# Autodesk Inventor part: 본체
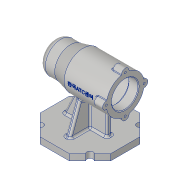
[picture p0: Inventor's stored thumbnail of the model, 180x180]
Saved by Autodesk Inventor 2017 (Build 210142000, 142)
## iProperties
Created: 2019-12
Part Number: 본체
Material: 알루미늄 6061
Document SubType Name: Modeling
Designer: 5-14-le-1
Density: 2.7 g/cm^3
Appearance: 알루미늄 - 평지
Mass: 725.806 g
Surface Area: 714.703 cm^2
Volume: 268.817 cm^3
Author: 5-14-le-1
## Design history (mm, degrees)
sketch "스케치1"
  geometry: 1 further point
sketch "스케치2"
  geometry: L1 (56, 23.196)-(56, -23.196); L2 (23.196, -56)-(-23.196, -56); L3 (-56, -23.196)-(-56, 23.196); L4 (-23.196, 56)-(23.196, 56); L5 (0, 0)-(-39.598, 39.598); L6 (0, 0)-(-39.598, -39.598); L7 (0, 0)-(39.598, 39.598); L8 (0, 0)-(39.598, -39.598); L9 (56, -23.196)-(43.134, -36.062); L10 (36.062, -43.134)-(23.196, -56); L11 (-23.196, -56)-(-36.062, -43.134); L12 (-43.134, -36.062)-(-56, -23.196); L13 (23.196, 56)-(36.062, 43.134); L14 (43.134, 36.062)-(56, 23.196); L15 (-56, 23.196)-(-43.134, 36.062); L16 (-36.062, 43.134)-(-23.196, 56); A1 r 56 centre (0, 0) between (0, 56) and (39.598, 39.598); A2 r 5 centre (-39.598, 39.598) between (-43.134, 36.062) and (-36.062, 43.134); A3 r 5 centre (39.598, 39.598) between (36.062, 43.134) and (43.134, 36.062); A4 r 5 centre (39.598, -39.598) between (43.134, -36.062) and (36.062, -43.134); A5 r 5 centre (-39.598, -39.598) between (-36.062, -43.134) and (-43.134, -36.062); 1 further point
  constraints: 32 end point, 11 point on circle, 5 centre point, 5 coincident, 1 midpoint, 9 other
  dimensions: "d0" = 112 diameter of A1; "d1" = 10 diameter of A2; "d2" = 10 diameter of A3; "d3" = 10 diameter of A4; "d4" = 10 diameter of A5
extrude "돌출1" new body sketch "스케치2" distance "d5" = 10; taper "d6" = 0 deg
sketch "스케치3"
  geometry: L1 (-38, -4)-(31, -4); L2 (31, -4)-(31, 4); L3 (31, 4)-(-38, 4); L4 (-38, 4)-(-38, -4); L5 (-4, 36)-(4, 36); L6 (4, 36)-(4, -36); L7 (4, -36)-(-4, -36); L8 (-4, -36)-(-4, 36); L9 (-4, 36)-(4, -36); L10 (4, 36)-(-4, -36); L11 (56, -23.196)-(56, 23.196) reference; L12 (-56, 23.196)-(-56, -23.196) reference; 1 further point
  constraints: 20 end point, 4 parallel, 2 horizontal, 2 midpoint, 2 perpendicular
  dimensions: "d7" = 8 distance of L1.end L2.end; "d8" = 8 distance of L6.end L7.end; "d10" = 72 distance of L5.end L6.end; "d64" = 18 distance between parallel lines of L4 L12; "d65" = 25 distance between parallel lines of L11 L2
extrude "돌출2" join sketch "스케치3" distance "d11" = 70; taper "d12" = 0 deg
sketch "스케치4"
  geometry: L1 (34, 0)-(34, 70) reference; L2 (0, 70)-(34, 70) reference; L3 (0, 0)-(32.642, 70); L4 (-18, 0)-(-5.134, 0) reference; L5 (0, 70)-(32.642, 70); L6 (0, 70)-(0, 0); L7 (1.938, 0)-(14.804, 0) reference; 2 further points
  constraints: 6 end point, 1 collinear, 1 perpendicular, 1 point on line
  dimensions: "d13" = 115 deg angle of L4 L3
extrude "돌출3" cut sketch "스케치4" distance "d14" = 70; taper "d15" = 0 deg
sketch "스케치5"
  geometry: L1 (0, 0)-(0, 70) reference; L2 (32, 0)-(0, 87.919); L3 (39.134, 0)-(52, 0) reference; L4 (0, 87.919)-(32, 87.919); L5 (32, 87.919)-(32, 0); 1 further point
  constraints: 6 end point, 1 horizontal, 1 perpendicular, 1 point on line
  dimensions: "d16" = 110 deg angle of L3 L2
extrude "돌출4" cut sketch "스케치5" distance "d17" = 70; taper "d18" = 0 deg
sketch "스케치6"
  geometry: L1 (0, 0)-(0, 80); L2 (-4, 80)-(4, 80) reference; L3 (56, 80)-(56, 110); L4 (31, 10)-(31, 80) reference; L5 (56, 110)-(-11, 110); L6 (56, 80)-(-56, 80); L7 (-56, 80)-(-56, 105); L8 (-56, 105)-(-31, 105); L9 (-31, 105)-(-11, 110)
  constraints: 14 end point, 2 horizontal, 2 vertical, 1 midpoint, 1 perpendicular
  dimensions: "d20" = 30 distance of L3.start L3.end; "d21" = 25 distance from line of L3.start L4; "d22" = 67 distance of L3.end L5.end; "d24" = 112 distance of L3.start L6.end; "d25" = 25 distance of L6.end L7.end; "d26" = 25 distance of L7.end L8.end; "d27" = 45 horizontal distance of L5.end L7.end (derived)
revolve "회전1" sketch "스케치6" stored, may be unused: angle "d28" = 90 deg
fillet "모깎기1" dims "d29" = 10
sketch "스케치7"
  geometry: C1 r 30 at (0, 0) reference; C2 r 21 at (0, 0); 1 further point
  constraints: 1 centre point, 1 coincident
  dimensions: "d30" = 42 diameter of C2
extrude "돌출5" cut sketch "스케치7" distance "d31" = 15; taper "d32" = 0 deg
sketch "스케치8"
  geometry: C1 r 21 at (0, 0) reference; C2 r 24 at (0, 0); 1 further point
  constraints: 1 centre point, 1 coincident
  dimensions: "d33" = 48 diameter of C2
extrude "돌출6" cut sketch "스케치8" distance "d34" = 54; taper "d35" = 0 deg
sketch "스케치9"
  geometry: C1 r 24 at (0, 0) reference; C2 r 21 at (0, 0); 1 further point
  constraints: 1 centre point, 1 coincident
  dimensions: "d36" = 42 diameter of C2
extrude "돌출7" cut sketch "스케치9" distance "d37" = 12; taper "d38" = 0 deg
sketch "스케치10"
  geometry: C1 r 21 at (0, 0) reference; C2 r 17.5 at (0, 0); 1 further point
  constraints: 1 centre point, 1 coincident
  dimensions: "d39" = 35 diameter of C2
extrude "돌출8" cut sketch "스케치10" distance "d40" = 18; taper "d41" = 0 deg
sketch "스케치11"
  geometry: C1 r 17.5 at (0, 0) reference; C2 r 16 at (0, 0); 1 further point
  constraints: 1 centre point, 1 coincident
  dimensions: "d42" = 32 diameter of C2
extrude "돌출9" cut sketch "스케치11" distance "d43" = 4; taper "d44" = 0 deg
sketch "스케치12"
  geometry: C1 r 6 at (0, 30); C2 r 6 at (30, 0); C3 r 6 at (-30, 0); C4 r 6 at (0.076, -30); A1 r 30 centre (0, 0) between (0, 30) and (30, 0) reference; A2 r 30 centre (0, 0) between (-4, -29.732) and (4, -29.732) reference; 1 further point
  constraints: 5 point on circle, 4 centre point
  dimensions: "d46" = 12 diameter of C1; "d47" = 12 diameter of C2; "d48" = 12 diameter of C3; "d49" = 12 diameter of C4
extrude "돌출10" join sketch "스케치12" distance "d50" = 16; taper "d51" = 0 deg
sketch "스케치13"
  geometry: A1 r 6 centre (-30, 30) between (-24.03, 29.4) and (-35.97, 29.4) reference; 2 further points
  constraints: 1 coincident
hole "구멍1" sketch "스케치13" at (-30, 30) diameter "d53" = 3.242; stored, may be unused: countersink angle "d57" = 90 deg, drill point angle "d59" = 118 deg; dims "d54" = 8, "d55" = 4, "d56" = 2, "d58" = 11
fillet "모깎기4" dims "d63" = 3
fillet "모깎기5" dims "d66" = 3
fillet "모깎기6" dims "d67" = 3
fillet "모깎기7" dims "d68" = 3
fillet "모깎기8" dims "d69" = 1
sketch "스케치14"
  geometry: 1 further point
sketch "스케치15"
  geometry: C1 r 16 at (0, 0) reference; C2 r 10.5 at (0, 0); 1 further point
  constraints: 1 centre point, 1 coincident
  dimensions: "d70" = 21 diameter of C2
extrude "돌출11" cut sketch "스케치15" distance "d71" = 3; taper "d72" = 0 deg
fillet "모깎기9" dims "d73" = 3
fillet "모깎기10" dims "d74" = 0.3
node "작업 평면1"
sketch "스케치16"
  geometry: L1 (-28.239, 3.002)-(13.239, 3.002); L2 (13.239, 3.002)-(13.239, -3.002); L3 (13.239, -3.002)-(-28.239, -3.002); L4 (-28.239, -3.002)-(-28.239, 3.002); L5 (-7.5, 3.002)-(-7.5, -3.002); L6 (13.239, 0)-(-28.239, 0); L7 (33.5, 6.771)-(33.5, 29.226) reference; L8 (20.634, -80)-(33.5, -80) reference; 1 further point
  constraints: 4 end point, 4 midpoint, 2 other
  dimensions: "d75" = 41 distance between parallel lines of L7 L5; "d76" = 80 distance between parallel lines of L8 L6
feature "엠보싱1" sketch "스케치16" dims "d0" = 112, "d77" = 0.5, "d78" = 0
chamfer "모따기1" distance "d79" = 1; stored, may be unused: second distance "d80" = 2, angle "d81" = 45 deg
node "솔리드1"
mirror "미러1"
pattern_circular "원형 패턴1" dims angle "d61" = 360 deg
